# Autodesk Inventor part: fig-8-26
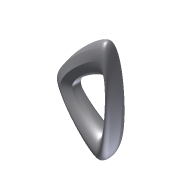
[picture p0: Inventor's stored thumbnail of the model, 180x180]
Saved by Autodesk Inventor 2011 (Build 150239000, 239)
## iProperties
Created: 2008-06
Part Number: fig-8-26
Document SubType Name: Modeling
Designer: CADCIM
Density: 1 g/cm^3
Author: CADCIM
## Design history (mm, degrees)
sketch "Sketch1"
  geometry: L1 (-0.077, 5.773)-(4.961, 2.953); L2 (4.961, 2.953)-(5.038, -2.82); L3 (5.038, -2.82)-(0.077, -5.773); L4 (0.077, -5.773)-(-4.961, -2.953); L5 (-4.961, -2.953)-(-5.038, 2.82); L6 (-5.038, 2.82)-(-0.077, 5.773); 1 further point
  constraints: 12 end point, 13 other
  dimensions: "d0" = 10 distance between parallel lines of L2 L5
workplane "Work Plane1"
sketch "Sketch2"
  geometry: C1 r 7.5 at (-0.159, -25); 1 further point
  constraints: 1 centre point
  dimensions: "d2" = 15 diameter of C1; "d3" = 25 vertical distance of C1.centre point (0, 0)
sketch "Sketch3" dims "d4" = 10, "d5" = 5
  geometry: 2 further points; 1 other entity
  constraints: 2 other
  dimensions: "d6" = 25 vertical distance of point (0.175, 25) point (0, 0)
loft "Loft1" sketch "Sketch2", "Sketch3" dims "d7" = 0, "d8" = 90 deg, "d9" = 0, "d10" = 90 deg, "d11" = 0, "d12" = 90 deg
body "Solid1"
other parameters: "d1" = 25
